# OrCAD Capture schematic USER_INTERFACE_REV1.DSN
size A; title: User Interface Schematic; rev: <Rev1>
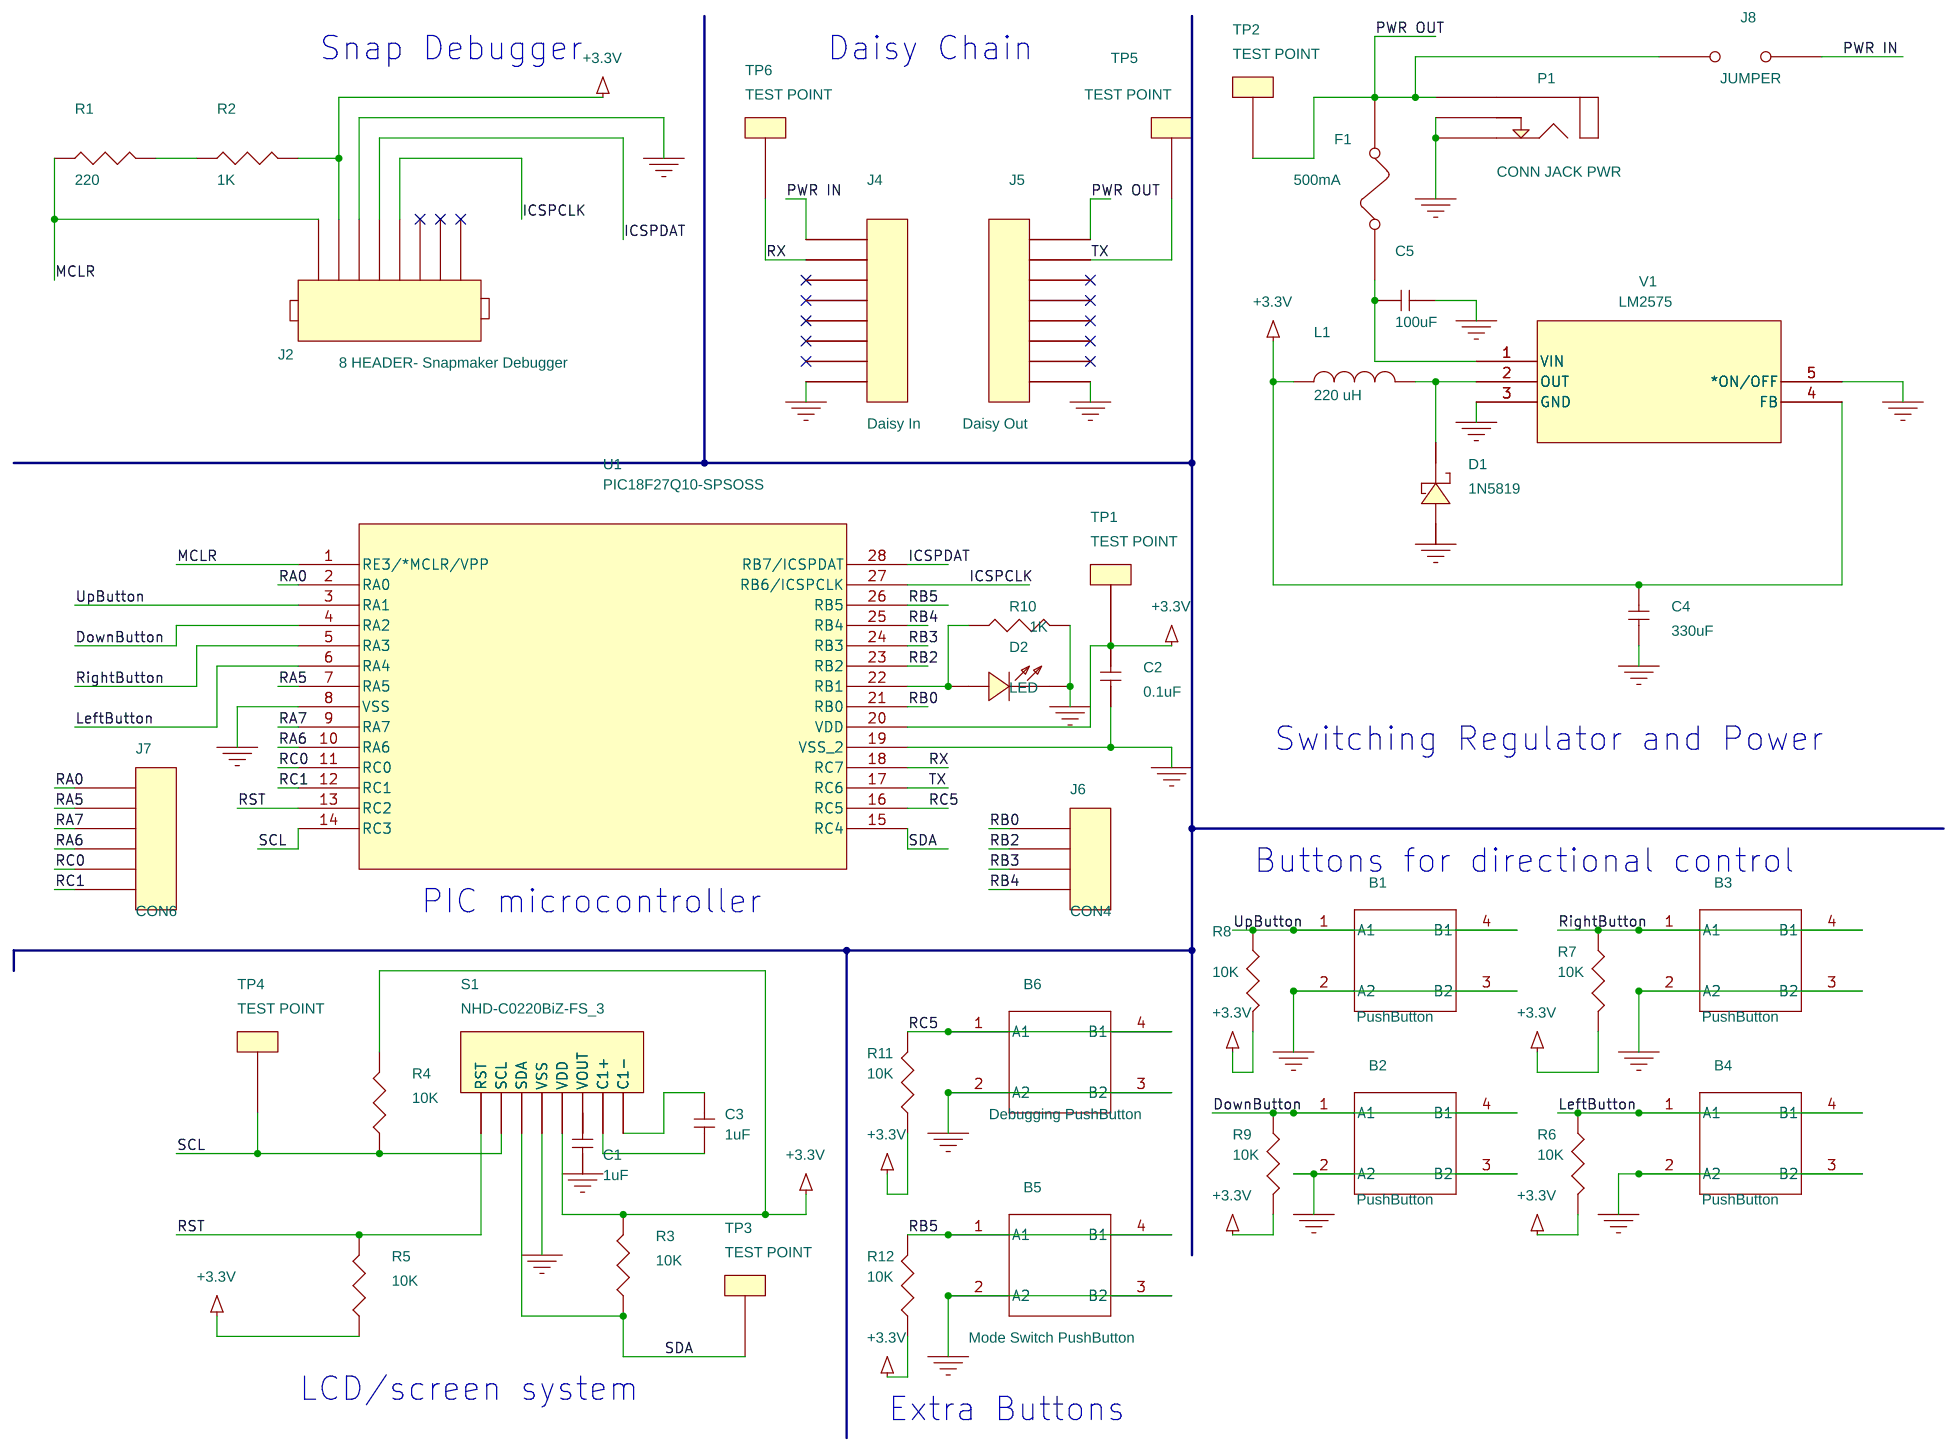
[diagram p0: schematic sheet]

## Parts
B1  PushButton
B2  PushButton
B3  PushButton
B4  PushButton
B5  Mode Switch PushButton
B6  Debugging PushButton
C1  1uF  [RAD/CK05]
C2  0.1uF  [RAD/CK05]
C3  1uF  [RAD/CK05]
C4  330uF  [RAD/CK05]
C5  100uF  [RAD/CK05]
D1  1N5819
D2  LED
F1  500mA
J2  8 HEADER- Snapmaker Debugger
J4  Daisy In
J5  Daisy Out
J6  CON4
J7  CON6
J8  JUMPER
L1  220 uH
P1  CONN JACK PWR
R1  220
R2  1K
R3  10K
R4  10K
R5  10K
R6  10K
R7  10K
R8  10K
R9  10K
R10  1K
R11  10K
R12  10K
S1  NHD-C0220BiZ-FS_3  [NHD-C0220BiZ-FS_NDI]
TP1  TEST POINT
TP2  TEST POINT
TP3  TEST POINT
TP4  TEST POINT
TP5  TEST POINT
TP6  TEST POINT
U1  PIC18F27Q10-SPSOSS  [SOIC28_SO_MCH]
V1  LM2575  [TO-263-5_T__MCH]

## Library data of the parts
B1-B6 = Button_4pin
C1-C5 = C: AppProp: InductiveSlave:;SRF:;PrevCap:1u;PrevESL:
D1 = DIODE_SCHOTTKY
D2 = LED
F1 = FUSE
J2 = 8_HEADER
J4 J5 = CON8
J6 = CON4
J7 = CON6
J8 = JUMPER
L1 = INDUCTOR
P1 = CONN_JACK_PWR
R1-R12 = RESISTOR
S1 = NHD-C0220BiZ-FS
TP1-TP6 = TEST_POINT
U1 = PIC18F27Q10T-ISO
V1 = LM2575-3P3WU-TR_0

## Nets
+3.3V: C2.2 C4.2 J2.2 L1.1 R2.2 R3.2 R4.2 R5.1 R6.2 R7.2 R8.2 R9.2 R11.1 R12.1 S1.5(VDD) TP1.1 U1.20(VDD) V1.4(FB)
GND: B1.2(A2) B1.3(B2) B2.2(A2) B2.3(B2) B3.2(A2) B3.3(B2) B4.2(A2) B4.3(B2) B5.2(A2) B5.3(B2) B6.2(A2) B6.3(B2) C1.1 C2.1 C4.1 C5.1 D1.1(ANODE) D2.1(CATHODE) J2.3 J4.8 J5.8 P1.2 P1.3 R10.2 S1.4(VSS) U1.8(VSS) U1.19(VSS_2) V1.3(GND) V1.5(*ON/OFF)
DownButton: B2.1(A1) B2.4(B1) R9.1 U1.4(RA2)
ICSPCLK: J2.5 U1.27(RB6/ICSPCLK)
ICSPDAT: J2.4 U1.28(RB7/ICSPDAT)
LeftButton: B4.1(A1) B4.4(B1) R6.1 U1.6(RA4)
MCLR: J2.1 R1.1 U1.1(RE3/*MCLR/VPP)
PWR IN: J4.1 J8.2
PWR OUT: F1.2 J5.1 J8.1 P1.1 TP2.1
RA0: J7.1 U1.2(RA0)
RA5: J7.2 U1.7(RA5)
RA6: J7.4 U1.10(RA6)
RA7: J7.3 U1.9(RA7)
RB0: J6.1 U1.21(RB0)
RB2: J6.2 U1.23(RB2)
RB3: J6.3 U1.24(RB3)
RB4: J6.4 U1.25(RB4)
RB5: B5.1(A1) B5.4(B1) R12.2 U1.26(RB5)
RC0: J7.5 U1.11(RC0)
RC1: J7.6 U1.12(RC1)
RC5: B6.1(A1) B6.4(B1) R11.2 U1.16(RC5)
RightButton: B3.1(A1) B3.4(B1) R7.1 U1.5(RA3)
RST: R5.2 S1.1(RST) U1.13(RC2)
RX: J4.2 TP6.1 U1.18(RC7)
SCL: R4.1 S1.2(SCL) TP4.1 U1.14(RC3)
SDA: R3.1 S1.3(SDA) TP3.1 U1.15(RC4)
TX: J5.2 TP5.1 U1.17(RC6)
UpButton: B1.1(A1) B1.4(B1) R8.1 U1.3(RA1)
N01597: R1.2 R2.1
N02799: C3.2 S1.7(C1+)
N02816: C3.1 S1.8(C1-)
N05849: D1.2(CATHODE) L1.2 V1.2(OUT)
N06927: C5.2 F1.1 V1.1(VIN)
N07895: C1.2 S1.6(VOUT)
N11648: D2.2(ANODE) R10.1 U1.22(RB1)

Not connected (* = marked no-connect by the designer): J2 6* 7* 8*; J4 3* 4* 5* 6* 7*; J5 3* 4* 5* 6* 7*

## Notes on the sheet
- Snap Debugger
- Daisy Chain
- Switching Regulator and Power
- Buttons for directional control
- PIC microcontroller
- LCD/screen system
- Extra Buttons
